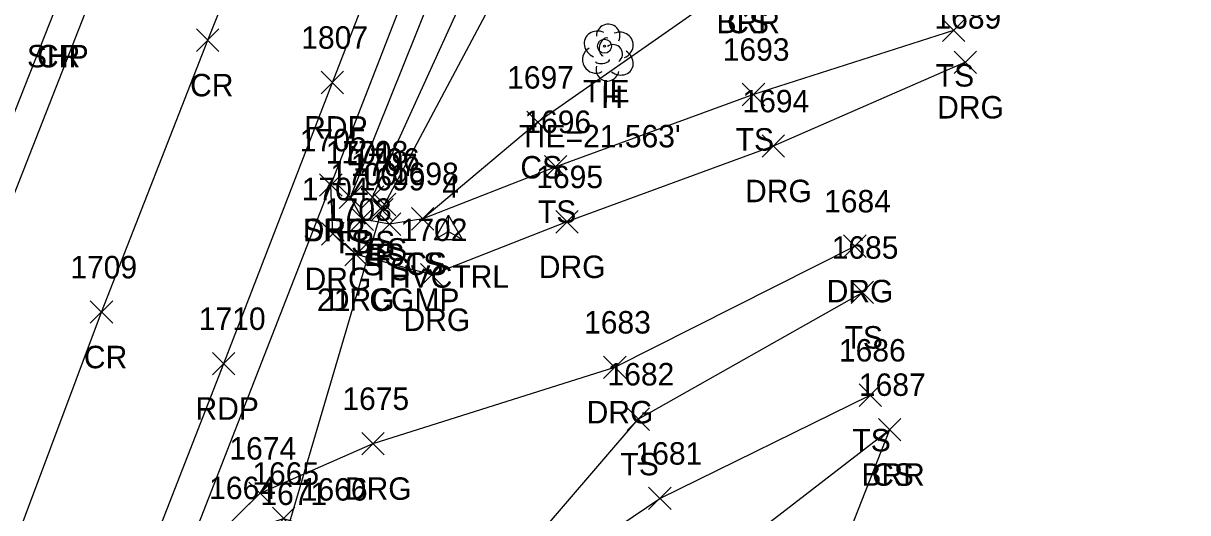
# Model space of a CAD drawing. Extents: x 1554917 to 1555870, y 813367 to 816333.
# Drawn here: x 1555258.8 to 1555362.5, y 814118 to 814161.6 of the extents above; entities that cross this region are included whole.
import ezdxf

# ---------------------------------------------------------------- set-up
doc = ezdxf.new("R2010")
doc.units = 0
for name, color, linetype in [('C_A', 7, 'Continuous'), ('C_C', 7, 'Continuous'), ('C_I', 7, 'Continuous'), ('CBP', 7, 'Continuous'), ('CPSM', 7, 'Continuous'), ('D_A', 7, 'Continuous'), ('D_C', 7, 'Continuous'), ('D_I', 7, 'Continuous'), ('D_TIC', 7, 'Continuous'), ('DCP', 7, 'Continuous'), ('L_A', 7, 'Continuous'), ('L_I', 7, 'Continuous'), ('L_TIC', 7, 'Continuous'), ('LABL', 7, 'Continuous'), ('LELB', 7, 'Continuous'), ('LTD', 7, 'Continuous'), ('P_A', 7, 'Continuous'), ('P_I', 7, 'Continuous'), ('P_TIC', 7, 'Continuous'), ('PET', 7, 'Continuous'), ('PRC', 7, 'Continuous'), ('PSP', 7, 'Continuous'), ('R_A', 7, 'Continuous'), ('R_I', 7, 'Continuous'), ('R_TIC', 7, 'Continuous'), ('RDG', 7, 'Continuous')]:
    doc.layers.add(name, color=color, linetype=linetype)

msp = doc.modelspace()

# ---------------------------------------------------------------- linework, layer by layer
at = {"layer": 'CBP'}
for radius in [0.625, 0.0833]:
    msp.add_circle((1555310.6, 814159.55), radius, dxfattribs=at)
at = {"layer": 'CPSM'}
for p, q in [((1555295.45, 814142.34), (1555296.7, 814144.51)), ((1555297.95, 814142.34), (1555296.7, 814144.51)), ((1555296.7, 814143.06), (1555296.7, 814144.51)), ((1555295.45, 814142.34), (1555296.7, 814143.06)), ((1555295.45, 814142.34), (1555297.95, 814142.34)), ((1555296.7, 814143.06), (1555296.7, 814143.06)), ((1555296.7, 814143.06), (1555297.95, 814142.34))]:
    msp.add_line(p, q, dxfattribs=at)
at = {"layer": 'D_TIC'}
for points in [[(1555289.78, 814143.99), (1555291.78, 814145.99)], [(1555291.78, 814143.99), (1555289.78, 814145.99)]]:
    msp.add_lwpolyline(points, dxfattribs=at)
at = {"layer": 'DCP'}
msp.add_lwpolyline([(1555282.12, 814115.72), (1555290.78, 814144.99)], dxfattribs=at)
at = {"layer": 'L_TIC'}
for points in [[(1555340.7, 814159.96), (1555342.7, 814161.96)], [(1555342.7, 814159.96), (1555340.7, 814161.96)], [(1555322.87, 814154.26), (1555324.87, 814156.26)], [(1555324.87, 814154.26), (1555322.87, 814156.26)], [(1555303.67, 814151.78), (1555305.67, 814153.78)], [(1555305.67, 814151.78), (1555303.67, 814153.78)], [(1555305.26, 814147.83), (1555307.26, 814149.83)], [(1555307.26, 814147.83), (1555305.26, 814149.83)], [(1555286.98, 814145.11), (1555288.98, 814147.11)], [(1555288.98, 814145.11), (1555286.98, 814147.11)], [(1555288.94, 814145.12), (1555290.94, 814147.12)], [(1555290.94, 814145.12), (1555288.94, 814147.12)], [(1555290.01, 814144.47), (1555292.01, 814146.47)], [(1555292.01, 814144.47), (1555290.01, 814146.47)], [(1555290.01, 814144.47), (1555292.01, 814146.47)], [(1555292.01, 814144.47), (1555290.01, 814146.47)], [(1555289.78, 814143.99), (1555291.78, 814145.99)], [(1555291.78, 814143.99), (1555289.78, 814145.99)], [(1555288.04, 814143.16), (1555290.04, 814145.16)], [(1555290.04, 814143.16), (1555288.04, 814145.16)], [(1555290.45, 814142.72), (1555292.45, 814144.72)], [(1555292.45, 814142.72), (1555290.45, 814144.72)], [(1555293.41, 814143.19), (1555295.41, 814145.19)], [(1555295.41, 814143.19), (1555293.41, 814145.19)], [(1555293.41, 814143.19), (1555295.41, 814145.19)], [(1555295.41, 814143.19), (1555293.41, 814145.19)], [(1555332.57, 814136.64), (1555334.57, 814138.64)], [(1555334.57, 814136.64), (1555332.57, 814138.64)], [(1555333.27, 814127.49), (1555335.27, 814129.49)], [(1555335.27, 814127.49), (1555333.27, 814129.49)], [(1555312.61, 814125.36), (1555314.61, 814127.36)], [(1555314.61, 814125.36), (1555312.61, 814127.36)], [(1555335, 814124.43), (1555337, 814126.43)], [(1555337, 814124.43), (1555335, 814126.43)], [(1555335, 814124.43), (1555337, 814126.43)], [(1555337, 814124.43), (1555335, 814126.43)], [(1555314.53, 814118.31), (1555316.53, 814120.31)], [(1555316.53, 814118.31), (1555314.53, 814120.31)], [(1555281.02, 814116.52), (1555283.02, 814118.52)], [(1555283.02, 814116.52), (1555281.02, 814118.52)]]:
    msp.add_lwpolyline(points, dxfattribs=at)
at = {"layer": 'LABL'}
msp.add_lwpolyline([(1555246.98, 813903.97), (1555255.51, 813921.27), (1555270.42, 813951.6), (1555277.93, 813973.79), (1555289.33, 813994.04), (1555300.33, 814008.73), (1555305.54, 814022.92), (1555313.64, 814041.1), (1555318.32, 814081.03), (1555326.1, 814100.25), (1555336, 814125.43)], dxfattribs=at)
at = {"layer": 'LELB'}
for points in [[(1555341.7, 814160.96), (1555323.87, 814155.26), (1555306.26, 814148.83), (1555294.41, 814144.19), (1555291.45, 814143.72), (1555289.04, 814144.16), (1555287.98, 814146.11), (1555302.24, 814181.58), (1555311.89, 814207.75), (1555329.49, 814252.62), (1555345.31, 814290.75), (1555356.6, 814322.62)], [(1555291.01, 814145.47), (1555290.78, 814144.99), (1555289.94, 814146.12), (1555305.56, 814180.39), (1555315.68, 814205.13), (1555332.52, 814252.13), (1555349.73, 814287.71), (1555359.86, 814320.99)], [(1555291.01, 814145.47), (1555308.8, 814178.88), (1555319.94, 814204.01), (1555335.36, 814250.39), (1555355.88, 814288.58), (1555362.55, 814319.62)], [(1555323.09, 814165.71), (1555304.67, 814152.78), (1555294.41, 814144.19)], [(1555244.11, 813903.09), (1555240.76, 813916.62), (1555228.48, 813937.37), (1555217.61, 813950.51), (1555215.58, 813954.88), (1555216.99, 813960.62), (1555222.34, 813976.41), (1555235.01, 814010.77), (1555239.56, 814017.88), (1555245.78, 814033.09), (1555255.18, 814058.98), (1555268.47, 814094.07), (1555274.97, 814112.22), (1555278.17, 814116.24), (1555282.02, 814117.52), (1555286.39, 814116.11), (1555289.99, 814109.88), (1555296.54, 814106.47), (1555313.61, 814126.36), (1555333.57, 814137.64)], [(1555296.54, 814106.47), (1555315.53, 814119.31), (1555334.27, 814128.49)], [(1555289.99, 814109.88), (1555288.26, 814106.9), (1555287.82, 814106.78), (1555296.74, 814101.9), (1555317.8, 814111.42), (1555336, 814125.43)]]:
    msp.add_lwpolyline(points, dxfattribs=at)
at = {"layer": 'LTD'}
msp.add_line((1555310.88, 814159.04), (1555310.88, 814159.04), dxfattribs=at)
msp.add_line((1555310.88, 814159.04), (1555310.88, 814159.04), dxfattribs=at)
msp.add_arc((1555310.93, 814160.47), 1.05, 335.5272, 180.9563, dxfattribs=at)
for centre, major_axis, ratio, start_param, end_param in [((1555310.09, 814159.7), (1.21, -0.51), 0.895232, 1.570796, 4.712389), ((1555311.93, 814159.62), (-1.14, -0.48), 0.949671, 1.570796, 4.712389), ((1555310.68, 814159.49), (-0.208, -0.792), 0.645439, 3.141593, 6.283185), ((1555309.8, 814158.33), (0.58, -1.04), 0.959034, 3.141593, 6.283185), ((1555311.38, 814158.87), (-0.5, 0.667), 0.989748, 3.141593, 6.283185), ((1555311.88, 814158.2), (-1.09, 0.79), 0.841452, 1.570796, 4.712389), ((1555310.88, 814157.54), (0.26, 1.06), 0.942809, 1.570796, 4.712389), ((1555310.43, 814158.29), (-0.625, -0.083), 0.423636, 0, 3.141593)]:
    msp.add_ellipse(centre, major_axis=major_axis, ratio=ratio, start_param=start_param, end_param=end_param, dxfattribs=at)
at = {"layer": 'P_TIC'}
for points in [[(1555274.26, 814159.09), (1555276.26, 814161.09)], [(1555276.26, 814159.09), (1555274.26, 814161.09)], [(1555285.36, 814155.33), (1555287.36, 814157.33)], [(1555287.36, 814155.33), (1555285.36, 814157.33)], [(1555285.23, 814146.2), (1555287.23, 814148.2)], [(1555287.23, 814146.2), (1555285.23, 814148.2)], [(1555264.8, 814134.89), (1555266.8, 814136.89)], [(1555266.8, 814134.89), (1555264.8, 814136.89)], [(1555275.68, 814130.3), (1555277.68, 814132.3)], [(1555277.68, 814130.3), (1555275.68, 814132.3)]]:
    msp.add_lwpolyline(points, dxfattribs=at)
at = {"layer": 'PET'}
for points in [[(1555161.36, 813900.53), (1555183.5, 813956.99), (1555189.63, 813971.7), (1555196.36, 813987.75), (1555203.89, 814008), (1555206.01, 814012.95), (1555218.07, 814043.52), (1555227.32, 814068.19), (1555240.79, 814103.21), (1555254.41, 814137.22), (1555273.72, 814186.43), (1555286.72, 814219.57), (1555303.34, 814262.32), (1555319.11, 814302.56), (1555330.34, 814331.97)], [(1555182.57, 813892.25), (1555203.7, 813945.01), (1555216.85, 813978.34), (1555228.72, 814008.85), (1555239.47, 814035.47), (1555248.64, 814059.88), (1555262.92, 814096.01), (1555276.68, 814131.3), (1555286.36, 814156.33), (1555297.11, 814184.04), (1555306.67, 814209.51), (1555324.28, 814253.26), (1555340.35, 814293.54), (1555352.6, 814325.05)]]:
    msp.add_lwpolyline(points, dxfattribs=at)
at = {"layer": 'PRC'}
msp.add_lwpolyline([(1554976.76, 813382.18), (1554992.84, 813427.9), (1555014.07, 813486.01), (1555030.62, 813532.31), (1555046.37, 813573.08), (1555064.69, 813621.19), (1555082.41, 813667.53), (1555112.1, 813744.1), (1555110.69, 813739.79), (1555136.16, 813805.74), (1555152.52, 813846.93), (1555172.03, 813896.18), (1555193.96, 813951.2), (1555206.37, 813983.4), (1555218.13, 814013.22), (1555228.65, 814039.26), (1555237.93, 814064.31), (1555252.22, 814099.76), (1555265.8, 814135.89), (1555275.26, 814160.09), (1555297.17, 814214.77), (1555313.83, 814257.94), (1555329.72, 814298.26), (1555342.03, 814329.92)], dxfattribs=at)
at = {"layer": 'PSP'}
for points in [[(1555160.79, 813906.47), (1555173.05, 813937.33), (1555179.42, 813953.63), (1555181.24, 813957.84), (1555186.72, 813973.16), (1555194.02, 813990.9), (1555204.38, 814016.29), (1555205.03, 814017.75), (1555215.29, 814044.5), (1555224.66, 814068.93), (1555238.68, 814103.48), (1555248.96, 814130.73), (1555261.62, 814162.67), (1555270.99, 814187.05), (1555283.98, 814220.8), (1555300.65, 814263.34), (1555316.51, 814303.51), (1555327.36, 814331.38)], [(1555197.67, 813922.42), (1555211.91, 813956.86), (1555220.23, 813977.15), (1555231.8, 814008.2), (1555242.48, 814034.48), (1555251.86, 814058.97), (1555266.04, 814094.8), (1555272.79, 814112.73), (1555286.23, 814147.2), (1555300.19, 814183.09), (1555310.34, 814208.22), (1555327.38, 814252.3), (1555343.49, 814292.44), (1555355.29, 814323.57)]]:
    msp.add_lwpolyline(points, dxfattribs=at)
at = {"layer": 'R_TIC'}
for points in [[(1555341.74, 814157.12), (1555343.74, 814159.12)], [(1555343.74, 814157.12), (1555341.74, 814159.12)], [(1555324.63, 814149.67), (1555326.63, 814151.67)], [(1555326.63, 814149.67), (1555324.63, 814151.67)], [(1555285.23, 814146.2), (1555287.23, 814148.2)], [(1555287.23, 814146.2), (1555285.23, 814148.2)], [(1555306.26, 814142.92), (1555308.26, 814144.92)], [(1555308.26, 814142.92), (1555306.26, 814144.92)], [(1555285.4, 814141.85), (1555287.4, 814143.85)], [(1555287.4, 814141.85), (1555285.4, 814143.85)], [(1555331.9, 814140.76), (1555333.9, 814142.76)], [(1555333.9, 814140.76), (1555331.9, 814142.76)], [(1555287.48, 814140.01), (1555289.48, 814142.01)], [(1555289.48, 814140.01), (1555287.48, 814142.01)], [(1555294.21, 814138.21), (1555296.21, 814140.21)], [(1555296.21, 814138.21), (1555294.21, 814140.21)], [(1555310.52, 814129.98), (1555312.52, 814131.98)], [(1555312.52, 814129.98), (1555310.52, 814131.98)], [(1555288.99, 814123.18), (1555290.99, 814125.18)], [(1555290.99, 814123.18), (1555288.99, 814125.18)], [(1555278.93, 814118.76), (1555280.93, 814120.76)], [(1555280.93, 814118.76), (1555278.93, 814120.76)]]:
    msp.add_lwpolyline(points, dxfattribs=at)
at = {"layer": 'RDG'}
for points in [[(1555342.74, 814158.12), (1555325.63, 814150.67), (1555307.26, 814143.92), (1555295.21, 814139.21), (1555288.48, 814141.01), (1555286.4, 814142.85), (1555286.23, 814147.2)], [(1555272.79, 814112.73), (1555279.93, 814119.76), (1555289.99, 814124.18), (1555311.52, 814130.98), (1555332.9, 814141.76)]]:
    msp.add_lwpolyline(points, dxfattribs=at)

# ---------------------------------------------------------------- texts
at = {"layer": 'C_A'}
for s, p in [('TIE', (1555308.68, 814154.55)), ('HVCTRL', (1555291.4, 814138.06))]:
    msp.add_text(s, height=2, dxfattribs=at).set_placement(p)
at = {"layer": 'C_C'}
msp.add_text("TIE=21.563'", height=2, dxfattribs=at).set_placement((1555302.97, 814150.55))
at = {"layer": 'C_I'}
msp.add_text('4', height=2, dxfattribs=at).set_placement((1555296.14, 814146.06))
at = {"layer": 'D_A'}
msp.add_text('P', height=2, dxfattribs=at).set_placement((1555290.15, 814139.99))
at = {"layer": 'D_C'}
msp.add_text('21" CGMP', height=2, dxfattribs=at).set_placement((1555284.99, 814135.99))
at = {"layer": 'D_I'}
for s, p in [('1707', (1555288, 814147.99)), ('1671', (1555279.95, 814118.72))]:
    msp.add_text(s, height=2, dxfattribs=at).set_placement(p)
at = {"layer": 'L_A'}
for s, p in [('BRR', (1555320.58, 814160.71)), ('CS', (1555321.53, 814160.71)), ('TS', (1555340.11, 814155.96)), ('H', (1555310.32, 814154.04)), ('TS', (1555322.28, 814150.26)), ('CS', (1555303.11, 814147.78)), ('TS', (1555304.67, 814143.83)), ('TS', (1555286.39, 814141.11)), ('BS', (1555288.39, 814141.12)), ('BS', (1555289.46, 814140.47)), ('BS', (1555289.46, 814140.47)), ('TS', (1555287.45, 814139.16)), ('BS', (1555289.22, 814139.99)), ('TS', (1555292.82, 814139.19)), ('CS', (1555292.85, 814139.19)), ('TS', (1555289.86, 814138.72)), ('TS', (1555331.98, 814132.64)), ('TS', (1555332.68, 814123.49)), ('TS', (1555312.02, 814121.36)), ('BRR', (1555333.48, 814120.43)), ('CS', (1555334.44, 814120.43))]:
    msp.add_text(s, height=2, dxfattribs=at).set_placement(p)
at = {"layer": 'L_I'}
for s, p in [('1693', (1555321.13, 814158.26)), ('1697', (1555301.93, 814155.78)), ('1696', (1555303.46, 814151.83)), ('1701', (1555285.77, 814149.11)), ('1708', (1555287.17, 814149.12)), ('1706', (1555288.19, 814148.47)), ('1706', (1555288.19, 814148.47)), ('1707', (1555288, 814147.99)), ('1700', (1555286.19, 814147.16)), ('1699', (1555288.7, 814146.72)), ('1698', (1555291.67, 814147.19)), ('1698', (1555291.67, 814147.19)), ('1685', (1555330.83, 814140.64)), ('1686', (1555331.48, 814131.49)), ('1682', (1555310.87, 814129.36)), ('1687', (1555333.26, 814128.43)), ('1687', (1555333.26, 814128.43)), ('1681', (1555313.36, 814122.31)), ('1665', (1555279.23, 814120.52)), ('1664', (1555275.39, 814119.24)), ('1671', (1555279.95, 814118.72)), ('1666', (1555283.55, 814119.11))]:
    msp.add_text(s, height=2, dxfattribs=at).set_placement(p)
at = {"layer": 'P_A'}
for s, p in [('SHP', (1555259.16, 814157.67)), ('CR', (1555260.05, 814157.67)), ('CR', (1555273.69, 814155.09)), ('RDP', (1555283.85, 814151.33)), ('SHP', (1555283.76, 814142.2)), ('CR', (1555264.23, 814130.89)), ('RDP', (1555274.17, 814126.3))]:
    msp.add_text(s, height=2, dxfattribs=at).set_placement(p)
at = {"layer": 'P_I'}
for s, p in [('1807', (1555283.59, 814159.33)), ('1705', (1555283.46, 814150.2)), ('1709', (1555263.02, 814138.89)), ('1710', (1555274.47, 814134.3))]:
    msp.add_text(s, height=2, dxfattribs=at).set_placement(p)
at = {"layer": 'R_A'}
for p in [(1555340.23, 814153.12), (1555323.12, 814145.67), (1555283.72, 814142.2), (1555304.75, 814138.92), (1555283.89, 814137.85), (1555330.39, 814136.76), (1555285.96, 814136.01), (1555292.7, 814134.21), (1555309.01, 814125.98), (1555287.48, 814119.18)]:
    msp.add_text('DRG', height=2, dxfattribs=at).set_placement(p)
at = {"layer": 'R_I'}
for s, p in [('1689', (1555339.99, 814161.12)), ('1694', (1555322.89, 814153.67)), ('1705', (1555283.46, 814150.2)), ('1695', (1555304.52, 814146.92)), ('1704', (1555283.63, 814145.85)), ('1684', (1555330.16, 814144.76)), ('1703', (1555285.7, 814144.01)), ('1702', (1555292.44, 814142.21)), ('1683', (1555308.78, 814133.98)), ('1675', (1555287.25, 814127.18)), ('1674', (1555277.19, 814122.76))]:
    msp.add_text(s, height=2, dxfattribs=at).set_placement(p)

doc.saveas('drawing.dxf')
